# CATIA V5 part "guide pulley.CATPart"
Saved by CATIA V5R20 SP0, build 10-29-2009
Part number: guide pulley
Source: Unknown
Bounding box of the stored display mesh (mm): x -14.981 to -0.019, y -7.481 to 7.481, z 0 to 10
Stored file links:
  C:\Users\Ikarus\OneDrive - FH JOANNEUM\BAC - Arbeit 1\CAD Modell\CAD-Modell-Step files\Platzhalter\guide pulley.CATPart
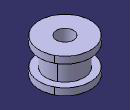
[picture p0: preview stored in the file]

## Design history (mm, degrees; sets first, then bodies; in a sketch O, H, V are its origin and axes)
Body1 (main body)
  Solid1 "Hauptkörper": solid without history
